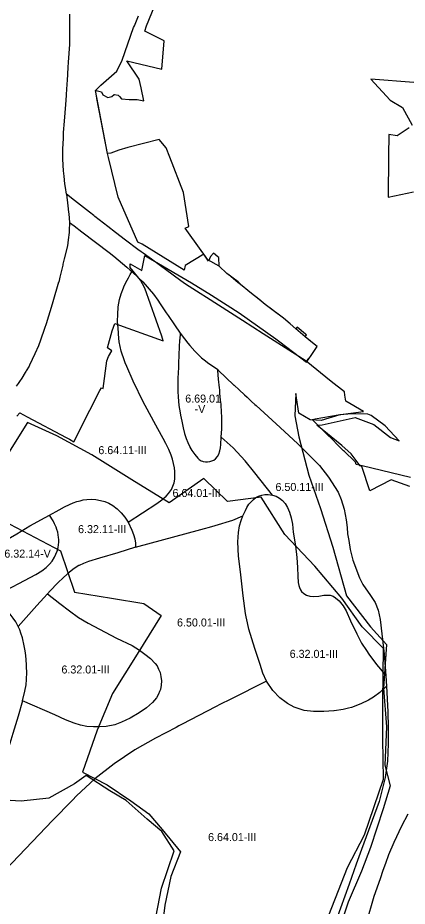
# Model space of a CAD drawing. Extents: x -555156 to -540209, y -1046851 to -1035695.
# Drawn here: x -542624 to -542138, y -1040556 to -1039446 of the extents above; entities that cross this region are included whole.
import ezdxf

# ---------------------------------------------------------------- set-up
doc = ezdxf.new("R2010")
doc.units = 0
for name, color, linetype in [('Vrstva 12', 7, 'Continuous'), ('Vrstva 27', 7, 'Continuous'), ('Vrstva 28', 7, 'Continuous'), ('Vrstva 29', 7, 'Continuous')]:
    doc.layers.add(name, color=color, linetype=linetype)

msp = doc.modelspace()

# ---------------------------------------------------------------- linework, layer by layer
at = {"layer": 'Vrstva 12'}
msp.add_lwpolyline([(-542625.85, -1039944.02), (-542621.93, -1039940.02), (-542612.66, -1039944.67), (-542563.91, -1039970.75), (-542559.87, -1039972.91), (-542554.562114, -1039976.245906), (-542534.56, -1039936.63), (-542522.15, -1039912.06), (-542520.07, -1039908.75), (-542517.77, -1039909.55), (-542513.5, -1039874.91), (-542511.05, -1039869.41), (-542507.09, -1039862.48), (-542512.355979, -1039858.552361), (-542506.75, -1039837.36), (-542503.20345, -1039828.061416), (-542443.07, -1039849.82), (-542444.69, -1039844.26), (-542465.85, -1039784.08), (-542471.27, -1039774.29), (-542484.288656, -1039758.339452), (-542484.07, -1039753.51), (-542469.498007, -1039761.988516), (-542465.82, -1039743.44), (-542407.75, -1039777.26), (-542382.79, -1039792.93), (-542347.98, -1039814.87), (-542302.42, -1039847.43), (-542297.11, -1039851.23), (-542264.011175, -1039876.68466), (-542258.25, -1039868.14), (-542251.51, -1039858.2), (-542250.76, -1039856.81), (-542256.48, -1039852.3), (-542265.87, -1039844.9), (-542264.19, -1039842.42), (-542265.4, -1039841.38), (-542275.5, -1039832.65), (-542277.17, -1039835.04), (-542284.42, -1039828.81), (-542292.74, -1039821.65), (-542304.03, -1039813.43), (-542307.82, -1039810.48), (-542315.49, -1039804.49), (-542323.66, -1039797.7), (-542332.71, -1039790.7), (-542337.19, -1039787.11), (-542344.34, -1039781.38), (-542349.33, -1039776.34), (-542363.53, -1039765.58), (-542373.21, -1039756.58), (-542373.46, -1039745.98), (-542373.67, -1039745.8), (-542374.85, -1039744.83), (-542380.32, -1039740.3), (-542383.9, -1039744.62), (-542386.16, -1039750.57), (-542392.4, -1039741.5), (-542395.73, -1039736.85), (-542415.67, -1039709), (-542411.11, -1039707.12), (-542417.48, -1039664.7), (-542434.7, -1039620.4), (-542439.2, -1039608.82), (-542448.16, -1039598.28), (-542486.94, -1039608.57), (-542498.15, -1039611.55), (-542508.34, -1039615.29), (-542512.31, -1039615.79), (-542527.42, -1039537.1), (-542520.94, -1039530.44), (-542501, -1039512.98), (-542494.25, -1039499.38), (-542479.99, -1039458.36), (-542478.96, -1039456.24), (-542473.9, -1039444.11)], dxfattribs=at)
at = {"layer": 'Vrstva 28'}
for points in [[(-542264.49, -1039875.43), (-542258.25, -1039868.14), (-542251.51, -1039858.2), (-542250.76, -1039856.81), (-542256.48, -1039852.3), (-542259.43, -1039849.98), (-542265.87, -1039844.9), (-542277.17, -1039835.04), (-542284.42, -1039828.81), (-542292.74, -1039821.65), (-542301.16, -1039815.52), (-542304.03, -1039813.43), (-542307.45, -1039810.93), (-542315.49, -1039804.49), (-542323.06, -1039798.43), (-542332.71, -1039790.7), (-542337.19, -1039787.11), (-542344.34, -1039781.38), (-542349.71, -1039777.08), (-542361.13, -1039767.58), (-542363.53, -1039765.58), (-542373.21, -1039756.58), (-542387.26, -1039748.68), (-542392.4, -1039741.5), (-542415.36, -1039755.88), (-542416.82, -1039761.66), (-542425.69, -1039756.13), (-542468.98, -1039729.2), (-542474.7, -1039726.68), (-542499.07, -1039670.62), (-542511.07, -1039620.92), (-542512.31, -1039615.79), (-542525.62, -1039547.18), (-542526.21, -1039543.88), (-542527.42, -1039537.1), (-542524.83, -1039537.67), (-542519.83, -1039538.75), (-542518.1, -1039542.5), (-542512, -1039546.1), (-542507.2, -1039544.5), (-542504.3, -1039542.2), (-542503.88, -1039542.2), (-542499.19, -1039543.22), (-542497.4, -1039544.6), (-542495, -1039547.8), (-542485.5, -1039548.3), (-542475.3, -1039548.6), (-542475.27, -1039548.39), (-542466.98, -1039550.18), (-542470.54, -1039533.8), (-542472.85, -1039523.15), (-542488.53, -1039500.1), (-542444.7, -1039510.58), (-542441.59, -1039475.01), (-542465.86, -1039463.25), (-542463.78, -1039456.45), (-542440.83, -1039400.18)], [(-542563.85, -1039666.49), (-542565.05, -1039658.26), (-542565.68, -1039653.94), (-542566.63, -1039644.16), (-542567.25, -1039637.72), (-542568.04, -1039623.08), (-542568.26, -1039610.48), (-542568.26, -1039610.33), (-542567.58, -1039596.8), (-542567.22, -1039589.66), (-542566.07, -1039575.71), (-542564.34, -1039554.62), (-542563.64, -1039543.41), (-542563.51, -1039541.35), (-542563.21, -1039536.56), (-542562.74, -1039528.99), (-542562.48, -1039524.74), (-542561.47, -1039508.59), (-542561.01, -1039501.72), (-542559.54, -1039479.86), (-542559.32, -1039476.62), (-542559.51, -1039441.98)], [(-542129.93, -1039527.19), (-542183.68, -1039522.92), (-542159.56, -1039549.14), (-542144.12, -1039558.27), (-542131.95, -1039580.38)], [(-542135.92, -1039583.92), (-542150.99, -1039593.79), (-542161.19, -1039592.21), (-542161.44, -1039619.33), (-542161.9, -1039670.27), (-542130.45, -1039663.89)], [(-542563.85, -1039666.49), (-542561.83, -1039681.27), (-542560.98, -1039689.27), (-542560.78, -1039691.21), (-542560, -1039701.93)], [(-542264.49, -1039875.43), (-542290.85, -1039858.55), (-542318.14, -1039841.08), (-542343.79, -1039824.66), (-542388.93, -1039795.76), (-542396.76, -1039790.75), (-542415.13, -1039778.98), (-542420.87, -1039774.81), (-542457.7, -1039748.07), (-542468.13, -1039740.5), (-542470.35, -1039738.88), (-542474.58, -1039735.72), (-542489.95, -1039724.24), (-542502.54, -1039714.4), (-542511.91, -1039707.08), (-542517.44, -1039702.76), (-542528.12, -1039694.42), (-542529.68, -1039693.2), (-542534.76, -1039689.23), (-542553.67, -1039674.45), (-542563.85, -1039666.49)], [(-542560, -1039701.93), (-542560.42, -1039712.27), (-542560.43, -1039712.56), (-542560.52, -1039714.74), (-542561.68, -1039723.86), (-542562.61, -1039731.22), (-542566.46, -1039747.32), (-542568.09, -1039754.16), (-542568.36, -1039755.28), (-542571.96, -1039770.52), (-542573.37, -1039776.46), (-542573.44, -1039776.75), (-542580.64, -1039801.14), (-542581.55, -1039804.21), (-542589.13, -1039828.79), (-542591.13, -1039834.47), (-542596.27, -1039849.06), (-542598.8, -1039856.26), (-542603.29, -1039866.07), (-542609.76, -1039880.18), (-542610.3, -1039881.36), (-542613.97, -1039887.34), (-542614.52, -1039888.23), (-542615.14, -1039889.24), (-542619.48, -1039896.32), (-542622.13, -1039900.64), (-542624.08, -1039903.29), (-542626.6, -1039906.71)], [(-542560, -1039701.93), (-542554.13, -1039706.38), (-542544.39, -1039713.76), (-542510.38, -1039739.55), (-542504.58, -1039743.95), (-542488.37, -1039757.82), (-542484.04, -1039761.61), (-542483.05, -1039762.48), (-542482.1, -1039763.31)], [(-542439.25, -1040043.78), (-542436.44, -1040040.59), (-542434.9, -1040038.83), (-542432.76, -1040035.67), (-542430.71, -1040031.49), (-542429.35, -1040027.39), (-542428.58, -1040022.52), (-542428.32, -1040017.48), (-542428.41, -1040013.04), (-542429.01, -1040008.6), (-542430.12, -1040003.05), (-542431.48, -1039997.58), (-542433.15, -1039992.51), (-542435.84, -1039985.63), (-542439.43, -1039978.31), (-542442.8, -1039972.06), (-542444.95, -1039968.08), (-542452.16, -1039955.34), (-542465.49, -1039930.76), (-542467.46, -1039926.72), (-542480.26, -1039900.42), (-542488.38, -1039881.87), (-542490.27, -1039877.55), (-542491.11, -1039875.04), (-542495.2, -1039862.76), (-542497.74, -1039851.1), (-542498.78, -1039841.5), (-542499.34, -1039832.92), (-542499.48, -1039830.7), (-542499.83, -1039825.36), (-542499.53, -1039816.84), (-542499.08, -1039807.27), (-542497.44, -1039798.46), (-542495.35, -1039791.13), (-542492.66, -1039783.81), (-542492.07, -1039782.61), (-542489.37, -1039777.09), (-542486.23, -1039771.11), (-542484.12, -1039767.13), (-542482.27, -1039763.63), (-542482.1, -1039763.31)], [(-542482.1, -1039763.31), (-542473.26, -1039771.65), (-542468.51, -1039776.12), (-542455.18, -1039791.55), (-542449.83, -1039799.25), (-542446.81, -1039803.58), (-542439.04, -1039814.92), (-542436.81, -1039818.17), (-542428.71, -1039829.93), (-542421.91, -1039840.13)], [(-542421.91, -1039840.13), (-542422.35, -1039848.21), (-542422.37, -1039848.6), (-542423.35, -1039866.85), (-542423.76, -1039878.79), (-542423.88, -1039882.17), (-542424.33, -1039890.52), (-542424.62, -1039895.77), (-542424.65, -1039898.23), (-542424.72, -1039903.2), (-542424.77, -1039907.12), (-542424.49, -1039913.18), (-542424.18, -1039919.98), (-542423.28, -1039930.59), (-542421.94, -1039939.85), (-542421.38, -1039942.6), (-542419.84, -1039950.17), (-542418.2, -1039958.38), (-542416.26, -1039965.6), (-542414.13, -1039971.83), (-542412.17, -1039976.96), (-542409.78, -1039982.34), (-542409.62, -1039982.64), (-542407.3, -1039986.95), (-542403.46, -1039992.07), (-542399.79, -1039996.51), (-542397.95, -1039998.23), (-542395.32, -1039999.79), (-542393.92, -1040000.21), (-542393.17, -1040000.43)], [(-542421.91, -1039840.13), (-542416.17, -1039847.54), (-542411.98, -1039852.95), (-542409.63, -1039855.66), (-542403.36, -1039862.89), (-542394.99, -1039871), (-542389.98, -1039874.97), (-542387.41, -1039877.01), (-542374.86, -1039885.9)], [(-542134.38, -1040020.74), (-542194.7, -1040006.17), (-542201.89, -1040004.43), (-542202.94, -1040001.27), (-542204.29, -1040000), (-542216.78, -1039988.21), (-542217.91, -1039987.15), (-542219.57, -1039985.58), (-542220.27, -1039984.88), (-542223.54, -1039981.6), (-542233.42, -1039971.67), (-542237.25, -1039967.82), (-542238.45, -1039966.61), (-542250.49, -1039954.52), (-542252.4, -1039952.6), (-542256.81, -1039948.17), (-542253.01, -1039947.47), (-542224.62, -1039942.22), (-542192.94, -1039938), (-542215.11, -1039925.2), (-542215.97, -1039917.69), (-542216.44, -1039913.53), (-542233.34, -1039900.68), (-542264.49, -1039875.43)], [(-542370.35, -1039970.31), (-542369.72, -1039959.71), (-542369.58, -1039957.33), (-542369.75, -1039945.8), (-542370.52, -1039930.86), (-542370.69, -1039929.13), (-542371.19, -1039923.94), (-542372.02, -1039915.35), (-542372.42, -1039911.19), (-542372.68, -1039908.54), (-542373.7, -1039897.92), (-542374.75, -1039887), (-542374.86, -1039885.9)], [(-542374.86, -1039885.9), (-542374.31, -1039886.43), (-542354.56, -1039905.23), (-542354.39, -1039905.39), (-542348.03, -1039911.27), (-542341.38, -1039917.42), (-542338.2, -1039920.36), (-542332.54, -1039925.59), (-542328.55, -1039929.28), (-542326.95, -1039930.76), (-542301.85, -1039953.51), (-542275.45, -1039978.1), (-542263.06, -1039990.16), (-542256.37, -1039996.66), (-542247.99, -1040005.62), (-542236.75, -1040020.27), (-542224.46, -1040038.84), (-542220.62, -1040047.88), (-542216.88, -1040060.28), (-542214.49, -1040073.43), (-542213.3, -1040083.15), (-542212.7, -1040090.99), (-542211.21, -1040099.36), (-542209.53, -1040110.68), (-542206.13, -1040124.02), (-542197.76, -1040145.73), (-542193.58, -1040154.35)], [(-542390.15, -1040000.87), (-542387.42, -1040000.82), (-542384.73, -1040000.43), (-542382.15, -1039999.79), (-542379.71, -1039998.77), (-542377.71, -1039997.21), (-542375.32, -1039994.43), (-542373.61, -1039991.4), (-542372.15, -1039987.15), (-542371.51, -1039983.45), (-542371.03, -1039979.2), (-542370.35, -1039970.31)], [(-542306.59, -1040042.52), (-542328.37, -1040014.72), (-542340.77, -1039999.63), (-542355.7, -1039983.63), (-542370.35, -1039970.31)], [(-542393.17, -1040000.43), (-542390.29, -1040000.87), (-542390.15, -1040000.87)], [(-542486.46, -1040076.42), (-542450.86, -1040053.26), (-542444.8, -1040048.4), (-542439.25, -1040043.78)], [(-542343.48, -1040068.62), (-542340.31, -1040061.9), (-542338.43, -1040057.97), (-542335.96, -1040054.05), (-542333.23, -1040050.89), (-542330.24, -1040048.07), (-542327.17, -1040045.42), (-542324.01, -1040043.97), (-542319.82, -1040042.6), (-542316.07, -1040041.92), (-542311.72, -1040042.01), (-542306.59, -1040042.52)], [(-542306.59, -1040042.52), (-542301.99, -1040044.05), (-542297.55, -1040046.53), (-542293.96, -1040049.18), (-542290.8, -1040053.02), (-542287.82, -1040058.15), (-542285.26, -1040063.95), (-542283.21, -1040071.13), (-542281.67, -1040079.07), (-542280.48, -1040088.8), (-542277.92, -1040105.93), (-542276.09, -1040120.65), (-542275.35, -1040133.05), (-542274.9, -1040143.96), (-542274.3, -1040151.74), (-542273.72, -1040155.47), (-542272.79, -1040158.2), (-542271.59, -1040160.77), (-542270.14, -1040162.9), (-542267.49, -1040165.63), (-542264.08, -1040167.68), (-542259.9, -1040168.71)], [(-542584.96, -1040067.51), (-542572.85, -1040060.91), (-542566.19, -1040057.24), (-542559.96, -1040054.25), (-542555.52, -1040052.37), (-542550.57, -1040050.58), (-542546.56, -1040049.55), (-542542.8, -1040048.7), (-542538.36, -1040048.1), (-542532.47, -1040047.76), (-542526.93, -1040048.19), (-542521.29, -1040049.23), (-542516, -1040050.77), (-542510.88, -1040052.65), (-542505.67, -1040055.64), (-542500.55, -1040059.82), (-542495.6, -1040064.69), (-542490.74, -1040070.16), (-542486.46, -1040076.42)], [(-542666.8, -1040117.35), (-542633.38, -1040095.5), (-542625.77, -1040090.87), (-542609.33, -1040080.86), (-542590.25, -1040070.4), (-542584.96, -1040067.51)], [(-542601.96, -1040141.62), (-542594.56, -1040137), (-542589.03, -1040132.82), (-542584.7, -1040128.78), (-542581.71, -1040124.9), (-542578.73, -1040119.97), (-542577.13, -1040116.5), (-542575.29, -1040112.49), (-542574.08, -1040108.03), (-542573.65, -1040104.52), (-542573.31, -1040101.19), (-542573.31, -1040098.03), (-542573.48, -1040095.39), (-542573.91, -1040092.06), (-542574.59, -1040088.73), (-542575.53, -1040085.39), (-542576.64, -1040082.49), (-542578.43, -1040078.48), (-542580.4, -1040074.81), (-542584.96, -1040067.51)], [(-542486.46, -1040076.42), (-542482.24, -1040086.36), (-542479.99, -1040091.89), (-542478.5, -1040097.27), (-542477.61, -1040102.5), (-542477.31, -1040107.43)], [(-542477.31, -1040107.43), (-542396.02, -1040085.62), (-542391.45, -1040084.27), (-542385.31, -1040082.46), (-542378.25, -1040080.39), (-542356.03, -1040073.85), (-542343.48, -1040068.62)], [(-542314.13, -1040275.05), (-542318.57, -1040264.85), (-542321.97, -1040254.12), (-542328.54, -1040234.05), (-542336.12, -1040209.99), (-542337.84, -1040202.05), (-542339.46, -1040194.53), (-542340.3, -1040190.64), (-542343.18, -1040168.41), (-542346.54, -1040138.33), (-542348.93, -1040118.75), (-542349.67, -1040100.82), (-542349.08, -1040089.31), (-542347.58, -1040080.94), (-542345.64, -1040074.36), (-542343.48, -1040068.62)], [(-542477.31, -1040107.43), (-542499.77, -1040114.6), (-542522.65, -1040121.43), (-542536.13, -1040125.53), (-542542.37, -1040127.93), (-542548, -1040130.49), (-542548.18, -1040130.6), (-542554.06, -1040134.24), (-542560.07, -1040138.88), (-542567.13, -1040145.15), (-542574.97, -1040152.74), (-542584.12, -1040162.15), (-542587.43, -1040165.91)], [(-542652.53, -1040168.27), (-542601.96, -1040141.62)], [(-542193.58, -1040154.35), (-542184.17, -1040167.95), (-542178.42, -1040176.84), (-542174.5, -1040186.25), (-542172.15, -1040197.76), (-542170.06, -1040215.81), (-542167.92, -1040233.67), (-542167.01, -1040241.32), (-542166.46, -1040245.88), (-542165, -1040268.34)], [(-542600.59, -1040180.46), (-542591.96, -1040171.05), (-542587.43, -1040165.91)], [(-542587.43, -1040165.91), (-542571.9, -1040178.18), (-542559.95, -1040187.06), (-542548.6, -1040195.26), (-542536.67, -1040202.4), (-542501.27, -1040221.08), (-542481.7, -1040230.64), (-542472.59, -1040236.32), (-542465.72, -1040241.25), (-542458.85, -1040246.78), (-542452.88, -1040252.72), (-542450.64, -1040256.01), (-542448.69, -1040259.9), (-542446.9, -1040264.08), (-542445.71, -1040269.16), (-542444.96, -1040274.54), (-542445.26, -1040280.07), (-542446.45, -1040285.6), (-542447.43, -1040288.02), (-542448.69, -1040291.13), (-542448.76, -1040291.25), (-542451.23, -1040295.77), (-542456.24, -1040301.71), (-542463.71, -1040308.13), (-542473.12, -1040314.71), (-542484.17, -1040321.28), (-542494.92, -1040326.36), (-542503.44, -1040329.35), (-542514.04, -1040331.45), (-542521.96, -1040332.04)], [(-542259.9, -1040168.71), (-542255.71, -1040169.05), (-542248.69, -1040168.64), (-542242.57, -1040167.74), (-542238.53, -1040167.59), (-542234.65, -1040167.74), (-542230.77, -1040168.79), (-542227.63, -1040170.88), (-542223.15, -1040174.62), (-542218.07, -1040180.89), (-542214.63, -1040187.32), (-542209.11, -1040199.43), (-542201.19, -1040216.01), (-542195.32, -1040227.48), (-542195.22, -1040227.67), (-542189.18, -1040236.88), (-542186.4, -1040241.12), (-542176.51, -1040253.98), (-542171.81, -1040260.13), (-542165, -1040268.34)], [(-542623.99, -1040206.54), (-542626.98, -1040201.07), (-542630.14, -1040196.12), (-542636.67, -1040187.81), (-542641.96, -1040181.24), (-542652.53, -1040168.27)], [(-542623.99, -1040206.54), (-542600.59, -1040180.46)], [(-542618.74, -1040299.52), (-542615.68, -1040287.69), (-542614.18, -1040279.47), (-542613.72, -1040273.01), (-542613.47, -1040269.52), (-542613.29, -1040267.07), (-542613.44, -1040254.36), (-542614.33, -1040242.86), (-542615.35, -1040236.96), (-542616.07, -1040232.76), (-542616.42, -1040230.75), (-542618.66, -1040220.89), (-542620.66, -1040215.08), (-542622.03, -1040211.06), (-542623.99, -1040206.54)], [(-542314.13, -1040275.05), (-542359.43, -1040297.76), (-542371.31, -1040303.71), (-542377.63, -1040306.87), (-542419.25, -1040328.84), (-542423.27, -1040330.93)], [(-542164.17, -1040281.3), (-542172.46, -1040289.31), (-542180.32, -1040295.04), (-542186.8, -1040298.62), (-542196.24, -1040303.29), (-542207.74, -1040307.74), (-542211.71, -1040308.73), (-542218.2, -1040310.36), (-542229.28, -1040312.12), (-542229.7, -1040312.19), (-542242.51, -1040312.97), (-542255.31, -1040312.97), (-542267.08, -1040311.66), (-542276.9, -1040308.32), (-542279.36, -1040307.48), (-542287.73, -1040303.03), (-542289.44, -1040301.73), (-542297.4, -1040295.71), (-542306.02, -1040286.82), (-542314.13, -1040275.05)], [(-542165, -1040268.34), (-542164.17, -1040281.13), (-542164.17, -1040281.3)], [(-542164.17, -1040281.3), (-542162.59, -1040313.22), (-542162.32, -1040318.6), (-542161.89, -1040327.35), (-542161.89, -1040350.2), (-542161.89, -1040353.44), (-542162.98, -1040375.05), (-542165.86, -1040395.45), (-542173.44, -1040425.26), (-542195.2, -1040485.09), (-542201.8, -1040503.71), (-542210.56, -1040528.46), (-542227.02, -1040573.44), (-542229.94, -1040581.38), (-542232.51, -1040588.39), (-542240.85, -1040611.09), (-542245.19, -1040622.89), (-542253.88, -1040646.81), (-542265.32, -1040678.33), (-542280.02, -1040713.71), (-542286.58, -1040732.12), (-542287.75, -1040735.39), (-542288.76, -1040738.22), (-542292.05, -1040747.44)], [(-542618.74, -1040299.52), (-542623.97, -1040318.61), (-542630.5, -1040340.32), (-542635.73, -1040357.05), (-542638.87, -1040369.35), (-542640.43, -1040380.07)], [(-542521.96, -1040332.04), (-542529.88, -1040332.19), (-542538.39, -1040331.6), (-542546.01, -1040329.95), (-542554.07, -1040327.41), (-542564.98, -1040323.23), (-542578.27, -1040316.95), (-542618.74, -1040299.52)], [(-542423.27, -1040330.93), (-542426.85, -1040332.79), (-542452.65, -1040346.23), (-542478.26, -1040360.88), (-542504.34, -1040378.27), (-542528.12, -1040397.03), (-542551, -1040418.09), (-542556.35, -1040423.61), (-542581.19, -1040449.21), (-542631.44, -1040501.76), (-542634.24, -1040504.69), (-542637.29, -1040507.88), (-542647.85, -1040518.92)], [(-542206.14, -1040646.59), (-542196.46, -1040606.05), (-542194.03, -1040596.4), (-542193.15, -1040592.91), (-542192.35, -1040589.71), (-542189.08, -1040576.69), (-542179.67, -1040543.74), (-542171.83, -1040521.51), (-542168.2, -1040511.01), (-542165.15, -1040502.22), (-542161.27, -1040491.46), (-542154.4, -1040476.07), (-542144.84, -1040455.59), (-542137.07, -1040440.65)]]:
    msp.add_lwpolyline(points, dxfattribs=at)
at = {"layer": 'Vrstva 29'}
for points in [[(-542135.028889, -1040031.928801), (-542158.42, -1040023.51), (-542184.94, -1040037.2), (-542194.950004, -1040006.897076), (-542197.141004, -1040006.188997), (-542208.33556, -1039991.070397), (-542219.78, -1039980.45), (-542251.17, -1039955.26), (-542244.42, -1039954.89), (-542203.41, -1039945.8), (-542179.75, -1039954.24), (-542159.327823, -1039970.594689), (-542148.340996, -1039974.683007), (-542165.957939, -1039955.936739), (-542183.31, -1039943.04), (-542187.46, -1039941.65), (-542207.42, -1039940.91), (-542222.42, -1039942.48), (-542245.5, -1039949.45), (-542259.27, -1039948.54), (-542273.7, -1039940.23), (-542277.368163, -1039915.571791), (-542278.513001, -1039943.563999), (-542273.465004, -1039969.987991), (-542261.226, -1040017.721007), (-542246.723009, -1040059.332992), (-542231.202995, -1040107.458), (-542214.152991, -1040168.547997), (-542183.907007, -1040206.924007), (-542164.287998, -1040229.205), (-542167.707002, -1040283.763002), (-542164.229002, -1040331.985999), (-542166.080993, -1040379.828), (-542159.429993, -1040405.675994), (-542168.491005, -1040434.506996), (-542183.959998, -1040482.770994), (-542195.161001, -1040512.369993), (-542212.020995, -1040551.105008), (-542225.747, -1040592.523004)], [(-542435.323975, -1040052.437012), (-542482.033997, -1040023.346985), (-542532.096985, -1039992.322021), (-542575.620911, -1039968.723999), (-542612.263, -1039951.828003), (-542680.112976, -1040059.549011)], [(-542243.72699, -1040586.223022), (-542212.925903, -1040507.836975), (-542191.559998, -1040467.036987), (-542167.89801, -1040397.252014), (-542168.89502, -1040347.536011), (-542168.617004, -1040300.016907), (-542167.976013, -1040234.388977), (-542194.434998, -1040207.202026), (-542220.096008, -1040171.162903), (-542253.755981, -1040131.356995), (-542291.262024, -1040091.603027), (-542320.549011, -1040045.159912), (-542362.666992, -1040050.619995), (-542392.004028, -1040021.810913), (-542435.323975, -1040052.437012)], [(-542642.503906, -1040074.770996), (-542595.031982, -1040099.606995), (-542571.184998, -1040112.166016), (-542553.78302, -1040163.838013), (-542507.330017, -1040171.422913), (-542467.156982, -1040178.002991), (-542445.658997, -1040193.093994), (-542475.219971, -1040241.46698), (-542506.10199, -1040290.19397), (-542525.400024, -1040336.211975), (-542543.650024, -1040388.490906), (-542513.036011, -1040404.413025), (-542483.153992, -1040424.338989), (-542461.018005, -1040440.528015), (-542444.15802, -1040460.179016), (-542421.500977, -1040488.184998), (-542433.492981, -1040519.077026), (-542440.84491, -1040554.632019), (-542444.956909, -1040588.317017)], [(-542454.404994, -1040581.157999), (-542445.100004, -1040533.381993), (-542429.054994, -1040487.107005), (-542444.457992, -1040462.700001), (-542462.837993, -1040447.214008), (-542488.988997, -1040423.897997), (-542509.585004, -1040411.983001), (-542539.022009, -1040392.622005), (-542553.839007, -1040403.125997), (-542585.666003, -1040421.062009), (-542620.415998, -1040424.843001), (-542655.264001, -1040422.988008)]]:
    msp.add_lwpolyline(points, dxfattribs=at)

# ---------------------------------------------------------------- texts
at = {"layer": 'Vrstva 27'}
for s, p in [('6.69.01', (-542415.403394, -1039927.01)), ('-V', (-542403.707227, -1039940.01)), ('6.64.11-III', (-542523.883926, -1039991.41)), ('6.50.11-III', (-542302.726548, -1040037.41)), ('6.64.01-III', (-542431.296548, -1040044.96)), ('6.32.11-III', (-542549.206548, -1040090.12)), ('6.32.14-V', (-542641.240884, -1040120.68)), ('6.50.01-III', (-542425.646548, -1040206.7)), ('6.32.01-III', (-542285.006548, -1040245.86)), ('6.32.01-III', (-542569.966548, -1040265.41)), ('6.64.01-III', (-542386.906548, -1040474.76))]:
    msp.add_text(s, height=10, dxfattribs=at).set_placement(p)

doc.saveas('drawing.dxf')
